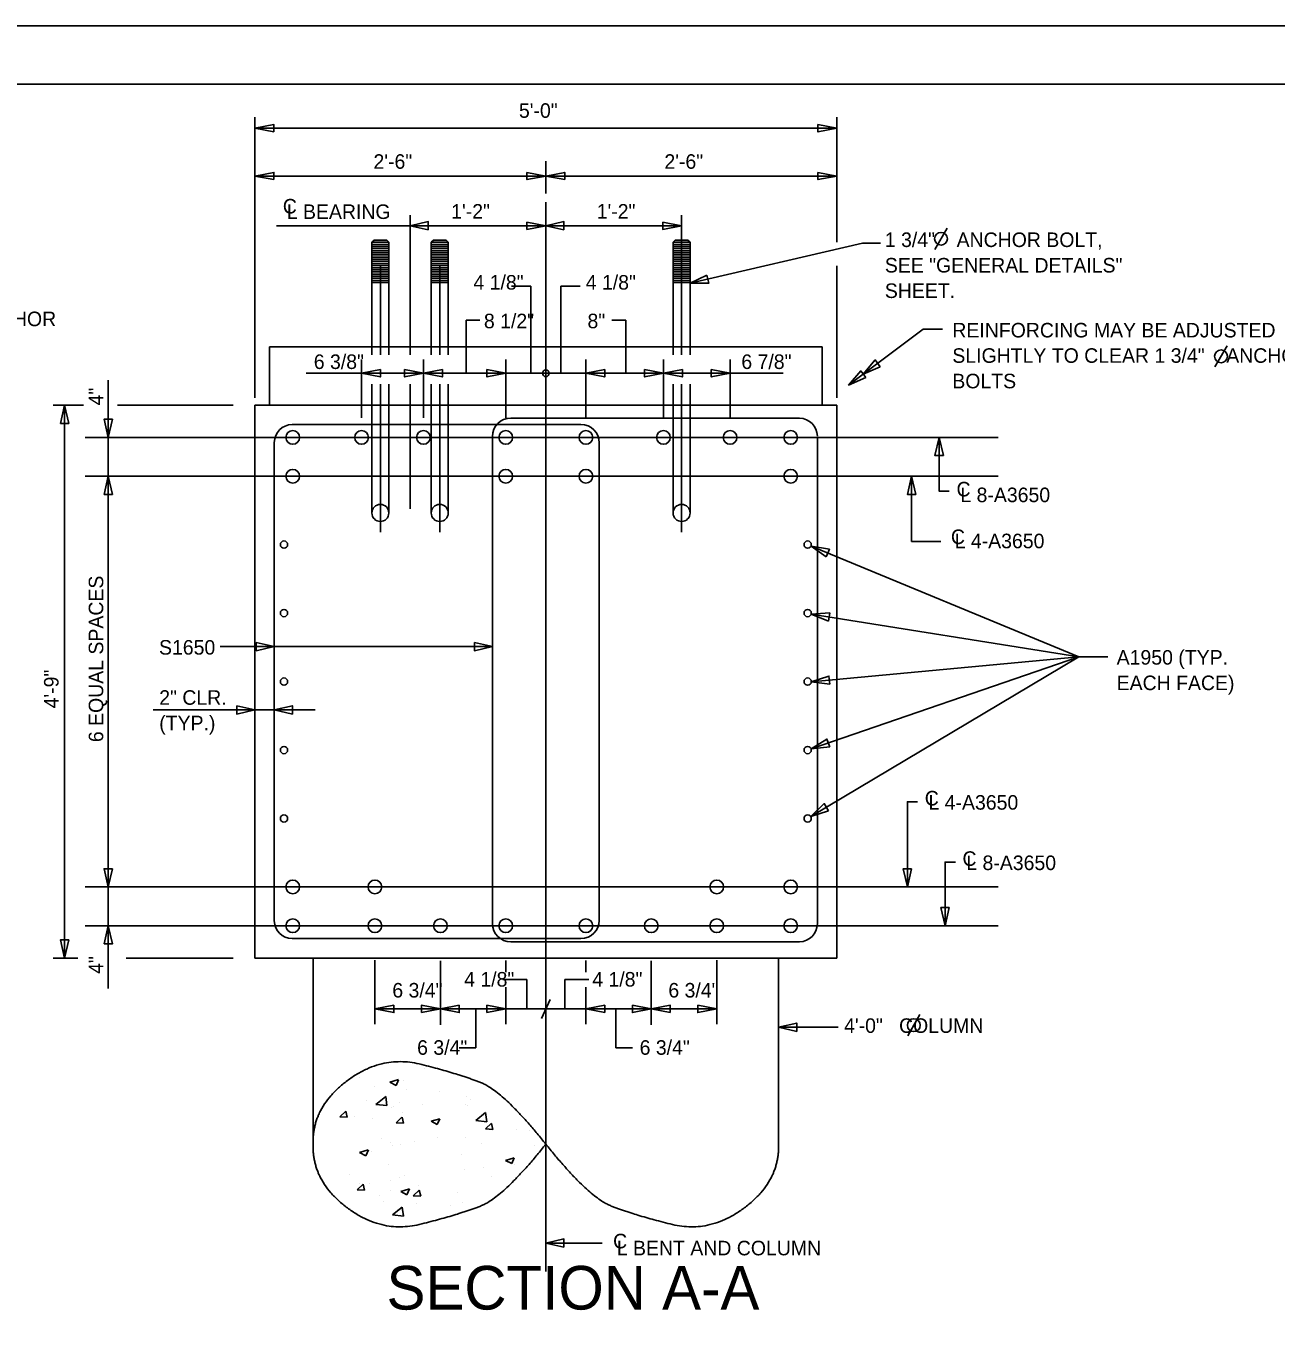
# Model space of a CAD drawing. Extents: x -133.1 to -97, y -1.7 to 20.3.
# Drawn here: x -120.43 to -109.68, y 9.2 to 20.31 of the extents above; entities that cross this region are included whole.
import ezdxf

# ---------------------------------------------------------------- set-up
doc = ezdxf.new("R2010")
doc.units = 0
for name, color, linetype in [('BR_AUTO DIMENSION', 7, 'Continuous'), ('BR_BORDER LINES', 7, 'Continuous'), ('BR_CENTER LINES', 7, 'Continuous'), ('BR_CONCRETE', 7, 'Continuous'), ('BR_REBAR', 7, 'Continuous'), ('BR_STRUCTURAL STEEL', 7, 'Continuous'), ('BR_TEXT', 7, 'Continuous'), ('Level 31', 7, 'Continuous')]:
    doc.layers.add(name, color=color, linetype=linetype)

msp = doc.modelspace()

# ---------------------------------------------------------------- linework, layer by layer
at = {"layer": 'BR_AUTO DIMENSION'}
for p, q in [((-118.457, 17.113), (-118.457, 19.526)), ((-113.457, 18.452), (-113.457, 19.526)), ((-118.457, 19.429), (-113.457, 19.429)), ((-115.957, 18.87), (-115.957, 19.147)), ((-118.457, 19.019), (-115.957, 19.019)), ((-113.457, 19.019), (-115.957, 19.019)), ((-118.271, 18.592), (-114.79, 18.592)), ((-114.717, 18.098), (-113.235, 18.442)), ((-113.235, 18.442), (-113.082, 18.442)), ((-113.457, 17.113), (-113.457, 18.247)), ((-116.087, 18.072), (-116.251, 18.072)), ((-116.087, 17.324), (-116.087, 18.072)), ((-115.827, 17.324), (-115.827, 18.072)), ((-115.827, 18.072), (-115.663, 18.072)), ((-116.642, 17.324), (-116.642, 17.78)), ((-116.642, 17.78), (-116.524, 17.78)), ((-115.271, 17.78), (-115.389, 17.78)), ((-115.271, 17.324), (-115.271, 17.78)), ((-117.54, 16.94), (-117.54, 17.443)), ((-117.009, 16.94), (-117.009, 17.443)), ((-116.301, 16.94), (-116.301, 17.443)), ((-115.613, 16.94), (-115.613, 17.443)), ((-114.946, 16.94), (-114.946, 17.443)), ((-114.373, 16.94), (-114.373, 17.443)), ((-119.717, 17.265), (-119.717, 12.039)), ((-118.017, 17.324), (-113.918, 17.324)), ((-119.93, 17.05), (-120.19, 17.05)), ((-120.092, 17.05), (-120.092, 12.3)), ((-118.644, 17.05), (-119.639, 17.05)), ((-112.814, 16.44), (-112.814, 15.878)), ((-111.376, 14.889), (-113.678, 15.839)), ((-112.814, 15.878), (-112.563, 15.878)), ((-111.376, 14.889), (-113.677, 15.254)), ((-116.415, 14.976), (-118.756, 14.976)), ((-111.376, 14.889), (-113.68, 13.516)), ((-111.376, 14.889), (-113.676, 14.673)), ((-117.939, 14.432), (-119.331, 14.432)), ((-119.979, 12.3), (-120.19, 12.3)), ((-118.644, 12.3), (-119.562, 12.3)), ((-117.426, 11.731), (-117.426, 12.282)), ((-116.863, 11.725), (-116.863, 12.277)), ((-116.301, 12.179), (-116.301, 12.278)), ((-115.613, 12.179), (-115.613, 12.278)), ((-115.051, 11.725), (-115.051, 12.277)), ((-114.488, 11.731), (-114.488, 12.282)), ((-116.119, 12.117), (-116.326, 12.117)), ((-116.119, 11.863), (-116.119, 12.117)), ((-115.794, 11.863), (-115.794, 12.117)), ((-115.794, 12.117), (-115.588, 12.117)), ((-116.301, 11.731), (-116.301, 12.049)), ((-115.613, 11.731), (-115.613, 12.049)), ((-115.994, 11.78), (-115.92, 11.945)), ((-114.488, 11.863), (-117.426, 11.863)), ((-116.558, 11.863), (-116.558, 11.53)), ((-115.356, 11.863), (-115.356, 11.53)), ((-113.957, 11.705), (-113.445, 11.705)), ((-116.558, 11.53), (-116.702, 11.53)), ((-115.355, 11.53), (-115.212, 11.53)), ((-115.957, 9.851), (-115.474, 9.851))]:
    msp.add_line(p, q, dxfattribs=at)
for points in [[(-118.294, 19.398), (-118.457, 19.429), (-118.294, 19.461)], [(-113.619, 19.461), (-113.457, 19.429), (-113.619, 19.398)], [(-118.294, 18.988), (-118.457, 19.019), (-118.294, 19.05)], [(-116.119, 19.05), (-115.957, 19.019), (-116.119, 18.988)], [(-115.794, 18.988), (-115.957, 19.019), (-115.794, 19.05)], [(-113.619, 19.05), (-113.457, 19.019), (-113.619, 18.988)], [(-116.968, 18.556), (-117.124, 18.592), (-116.968, 18.628)], [(-116.119, 18.623), (-115.957, 18.592), (-116.119, 18.56)], [(-115.801, 18.556), (-115.957, 18.592), (-115.801, 18.628)], [(-114.953, 18.623), (-114.79, 18.592), (-114.953, 18.56)], [(-114.573, 18.168), (-114.717, 18.098), (-114.557, 18.098)], [(-117.378, 17.356), (-117.54, 17.324), (-117.378, 17.293)], [(-117.171, 17.356), (-117.009, 17.324), (-117.171, 17.293)], [(-116.846, 17.356), (-117.009, 17.324), (-116.846, 17.293)], [(-116.463, 17.356), (-116.301, 17.324), (-116.463, 17.293)], [(-115.451, 17.356), (-115.613, 17.324), (-115.451, 17.293)], [(-115.109, 17.356), (-114.946, 17.324), (-115.109, 17.293)], [(-114.784, 17.356), (-114.946, 17.324), (-114.784, 17.293)], [(-114.536, 17.356), (-114.374, 17.324), (-114.536, 17.293)], [(-113.208, 17.288), (-113.355, 17.223), (-113.251, 17.345)], [(-113.083, 17.381), (-113.23, 17.316), (-113.126, 17.439)], [(-120.128, 16.894), (-120.092, 17.05), (-120.056, 16.894)], [(-119.681, 16.929), (-119.717, 16.773), (-119.753, 16.929)], [(-112.541, 16.617), (-112.577, 16.773), (-112.613, 16.617)], [(-119.753, 16.284), (-119.717, 16.44), (-119.681, 16.284)], [(-112.778, 16.284), (-112.814, 16.44), (-112.85, 16.284)], [(-113.548, 15.746), (-113.678, 15.839), (-113.52, 15.813)], [(-113.529, 15.194), (-113.677, 15.254), (-113.517, 15.265)], [(-118.446, 15.012), (-118.29, 14.976), (-118.446, 14.94)], [(-116.571, 15.012), (-116.415, 14.976), (-116.571, 14.94)], [(-113.517, 14.652), (-113.676, 14.673), (-113.524, 14.723)], [(-118.613, 14.468), (-118.457, 14.432), (-118.613, 14.396)], [(-118.134, 14.396), (-118.29, 14.432), (-118.134, 14.468)], [(-113.518, 14.114), (-113.677, 14.098), (-113.542, 14.182)], [(-113.528, 13.565), (-113.68, 13.516), (-113.565, 13.627)], [(-119.681, 13.067), (-119.717, 12.911), (-119.753, 13.067)], [(-112.814, 13.067), (-112.85, 12.911), (-112.886, 13.067)], [(-112.49, 12.734), (-112.526, 12.578), (-112.562, 12.734)], [(-119.753, 12.422), (-119.717, 12.578), (-119.681, 12.422)], [(-120.056, 12.456), (-120.092, 12.3), (-120.128, 12.456)], [(-117.263, 11.894), (-117.426, 11.863), (-117.263, 11.831)], [(-117.026, 11.831), (-116.863, 11.863), (-117.026, 11.894)], [(-116.701, 11.894), (-116.863, 11.863), (-116.701, 11.831)], [(-116.463, 11.831), (-116.301, 11.863), (-116.463, 11.894)], [(-115.451, 11.831), (-115.613, 11.863), (-115.451, 11.894)], [(-115.213, 11.894), (-115.051, 11.863), (-115.213, 11.831)], [(-114.888, 11.831), (-115.051, 11.863), (-114.888, 11.894)], [(-114.651, 11.894), (-114.488, 11.863), (-114.651, 11.831)], [(-113.801, 11.669), (-113.957, 11.705), (-113.801, 11.741)], [(-115.801, 9.815), (-115.957, 9.851), (-115.801, 9.887)]]:
    msp.add_lwpolyline(points, close=True, dxfattribs=at)
for points in [[(-113.355, 17.223), (-112.714, 17.702), (-112.549, 17.702)], [(-112.577, 16.773), (-112.577, 16.31), (-112.49, 16.31)], [(-113.677, 14.098), (-111.376, 14.889), (-111.129, 14.889)], [(-112.85, 12.911), (-112.85, 13.643), (-112.763, 13.643)], [(-112.526, 12.578), (-112.526, 13.124), (-112.438, 13.124)]]:
    msp.add_lwpolyline(points, dxfattribs=at)
msp.add_circle((-115.957, 17.324), 0.0285, dxfattribs=at)
at = {"layer": 'BR_BORDER LINES'}
msp.add_line((-97.642, 19.809), (-131.308, 19.809), dxfattribs=at)
at = {"layer": 'BR_CENTER LINES'}
for p, q in [((-115.957, 18.793), (-115.957, 9.608)), ((-117.124, 18.683), (-117.124, 17.482)), ((-114.79, 18.683), (-114.79, 17.482)), ((-117.379, 17.482), (-117.379, 18.257)), ((-116.869, 17.482), (-116.869, 18.257)), ((-114.79, 17.482), (-114.79, 18.257)), ((-117.379, 15.958), (-117.379, 17.23)), ((-117.124, 17.23), (-117.124, 16.161)), ((-116.869, 15.958), (-116.869, 17.23)), ((-114.79, 15.958), (-114.79, 17.23)), ((-119.915, 16.773), (-112.07, 16.773)), ((-119.915, 16.44), (-112.07, 16.44)), ((-119.915, 12.911), (-112.07, 12.911)), ((-119.915, 12.578), (-112.07, 12.578))]:
    msp.add_line(p, q, dxfattribs=at)
at = {"layer": 'BR_CONCRETE'}
for p, q in [((-118.332, 17.551), (-118.332, 17.05)), ((-118.332, 17.551), (-113.582, 17.551)), ((-113.582, 17.551), (-113.582, 17.05)), ((-118.457, 17.05), (-118.457, 12.3)), ((-118.457, 17.05), (-113.457, 17.05)), ((-113.457, 17.05), (-113.457, 12.3)), ((-118.457, 12.3), (-113.457, 12.3)), ((-117.957, 12.3), (-117.957, 10.669)), ((-113.957, 12.3), (-113.957, 10.668)), ((-117, 11.347), (-117, 11.347)), ((-117.558, 11.278), (-117.558, 11.278)), ((-117.297, 11.233), (-117.222, 11.256)), ((-117.297, 11.233), (-117.244, 11.205)), ((-117.243, 11.205), (-117.222, 11.255)), ((-117.177, 11.25), (-117.177, 11.25)), ((-117.432, 11.197), (-117.432, 11.197)), ((-117.156, 11.171), (-117.156, 11.171)), ((-116.87, 11.152), (-116.87, 11.152)), ((-117.502, 11.077), (-117.502, 11.077)), ((-117.417, 11.043), (-117.333, 11.111)), ((-117.417, 11.043), (-117.322, 11.032)), ((-117.322, 11.032), (-117.333, 11.111)), ((-117.282, 11.018), (-117.282, 11.018)), ((-117.262, 11.023), (-117.262, 11.023)), ((-117.216, 11.059), (-117.216, 11.059)), ((-117.014, 11.046), (-117.014, 11.046)), ((-116.644, 11.04), (-116.644, 11.04)), ((-116.637, 11.107), (-116.637, 11.107)), ((-116.633, 11.035), (-116.633, 11.035)), ((-116.608, 11.088), (-116.608, 11.088)), ((-117.727, 10.937), (-117.675, 10.985)), ((-117.727, 10.937), (-117.663, 10.933)), ((-117.663, 10.933), (-117.675, 10.985)), ((-117.673, 10.949), (-117.673, 10.949)), ((-117.601, 10.94), (-117.601, 10.94)), ((-117.445, 10.919), (-117.445, 10.919)), ((-117.244, 10.885), (-117.193, 10.933)), ((-117.18, 10.881), (-117.192, 10.933)), ((-117.19, 10.973), (-117.19, 10.973)), ((-116.943, 10.898), (-116.868, 10.92)), ((-116.943, 10.898), (-116.89, 10.87)), ((-116.89, 10.87), (-116.868, 10.92)), ((-116.559, 10.905), (-116.476, 10.973)), ((-116.559, 10.905), (-116.464, 10.894)), ((-116.464, 10.894), (-116.476, 10.973)), ((-117.244, 10.885), (-117.18, 10.881)), ((-116.476, 10.833), (-116.424, 10.881)), ((-116.476, 10.833), (-116.412, 10.828)), ((-116.412, 10.828), (-116.424, 10.88)), ((-116.213, 10.828), (-116.213, 10.828)), ((-116.096, 10.817), (-116.096, 10.817)), ((-117.369, 10.747), (-117.369, 10.747)), ((-117.296, 10.717), (-117.296, 10.717)), ((-117.278, 10.69), (-117.278, 10.69)), ((-117.203, 10.695), (-117.203, 10.695)), ((-117.083, 10.728), (-117.083, 10.728)), ((-116.89, 10.759), (-116.89, 10.759)), ((-116.646, 10.758), (-116.646, 10.758)), ((-116.511, 10.709), (-116.511, 10.709)), ((-116.056, 10.693), (-116.056, 10.693)), ((-117.558, 10.629), (-117.483, 10.651)), ((-117.558, 10.629), (-117.504, 10.601)), ((-117.504, 10.601), (-117.482, 10.651)), ((-117.458, 10.642), (-117.458, 10.642)), ((-116.681, 10.609), (-116.681, 10.609)), ((-116.303, 10.562), (-116.228, 10.585)), ((-116.303, 10.562), (-116.25, 10.534)), ((-116.25, 10.534), (-116.228, 10.584)), ((-117.306, 10.526), (-117.306, 10.526)), ((-116.659, 10.48), (-116.659, 10.48)), ((-116.495, 10.499), (-116.495, 10.499)), ((-116.227, 10.527), (-116.227, 10.527)), ((-116.109, 10.539), (-116.109, 10.539)), ((-117.645, 10.443), (-117.645, 10.443)), ((-117.578, 10.31), (-117.527, 10.358)), ((-117.56, 10.361), (-117.56, 10.361)), ((-117.514, 10.306), (-117.527, 10.358)), ((-117.471, 10.365), (-117.471, 10.365)), ((-117.292, 10.389), (-117.292, 10.389)), ((-117.216, 10.418), (-117.216, 10.418)), ((-117.172, 10.43), (-117.172, 10.43)), ((-117.049, 10.343), (-117.049, 10.343)), ((-116.424, 10.426), (-116.424, 10.426)), ((-117.578, 10.321), (-117.578, 10.321)), ((-117.578, 10.31), (-117.514, 10.306)), ((-117.388, 10.26), (-117.388, 10.26)), ((-117.292, 10.302), (-117.292, 10.302)), ((-117.204, 10.293), (-117.129, 10.316)), ((-117.204, 10.293), (-117.15, 10.265)), ((-117.15, 10.265), (-117.129, 10.316)), ((-117.096, 10.258), (-117.044, 10.306)), ((-117.096, 10.258), (-117.031, 10.254)), ((-117.031, 10.254), (-117.044, 10.306)), ((-116.72, 10.284), (-116.72, 10.284)), ((-117.352, 10.209), (-117.352, 10.209)), ((-117.275, 10.094), (-117.191, 10.161)), ((-117.229, 10.141), (-117.229, 10.141)), ((-117.179, 10.082), (-117.191, 10.161)), ((-117.066, 10.19), (-117.066, 10.19)), ((-116.777, 10.171), (-116.777, 10.171)), ((-116.672, 10.203), (-116.672, 10.203)), ((-117.275, 10.094), (-117.18, 10.082)), ((-117.168, 10.101), (-117.168, 10.101))]:
    msp.add_line(p, q, dxfattribs=at)
for points in [[(-117.957, 10.701), (-117.967, 11.017), (-117.368, 11.47), (-116.707, 11.307), (-116.318, 11.151), (-115.957, 10.701)], [(-117.957, 10.701), (-117.967, 10.384), (-117.368, 9.931), (-116.707, 10.094), (-116.318, 10.25), (-115.957, 10.701)], [(-113.957, 10.701), (-113.947, 10.384), (-114.546, 9.931), (-115.206, 10.094), (-115.595, 10.25), (-115.957, 10.701)]]:
    msp.add_open_spline(points, degree=2, dxfattribs=at)
at = {"layer": 'BR_REBAR'}
for p, q in [((-113.777, 16.938), (-116.259, 16.938)), ((-118.136, 16.884), (-115.655, 16.884)), ((-116.415, 16.782), (-116.415, 12.596)), ((-113.624, 16.779), (-113.624, 12.594)), ((-118.29, 16.73), (-118.29, 12.621)), ((-115.499, 16.728), (-115.499, 12.623)), ((-118.136, 12.467), (-115.655, 12.467)), ((-113.777, 12.44), (-116.259, 12.44))]:
    msp.add_line(p, q, dxfattribs=at)
for centre, radius in [((-118.132, 16.773), 0.0588), ((-117.54, 16.773), 0.0588), ((-117.009, 16.773), 0.0588), ((-116.301, 16.773), 0.0588), ((-115.613, 16.773), 0.0588), ((-114.946, 16.773), 0.0588), ((-114.374, 16.773), 0.0588), ((-113.853, 16.773), 0.0588), ((-118.132, 16.44), 0.0588), ((-116.301, 16.44), 0.0588), ((-115.613, 16.44), 0.0588), ((-113.853, 16.44), 0.0588), ((-118.207, 15.852), 0.0313), ((-113.707, 15.852), 0.0313), ((-118.207, 15.264), 0.0313), ((-113.707, 15.264), 0.0313), ((-118.207, 14.675), 0.0313), ((-113.707, 14.675), 0.0313), ((-118.207, 14.087), 0.0313), ((-113.707, 14.087), 0.0313), ((-118.207, 13.499), 0.0313), ((-113.707, 13.499), 0.0313), ((-118.132, 12.911), 0.0588), ((-117.426, 12.911), 0.0588), ((-114.488, 12.911), 0.0588), ((-113.853, 12.911), 0.0588), ((-118.132, 12.578), 0.0588), ((-117.426, 12.578), 0.0588), ((-116.863, 12.578), 0.0588), ((-116.301, 12.578), 0.0588), ((-115.613, 12.578), 0.0588), ((-115.051, 12.578), 0.0588), ((-114.488, 12.578), 0.0588), ((-113.853, 12.578), 0.0588)]:
    msp.add_circle(centre, radius, dxfattribs=at)
for centre, start, end in [((-116.259, 16.782), 90, 180), ((-113.78, 16.782), 1.025, 88.975), ((-118.134, 16.728), 91.025, 178.975), ((-115.655, 16.728), 0, 90), ((-118.134, 12.623), 181.025, 268.975), ((-116.259, 12.596), 180, 270), ((-115.655, 12.623), 270, 0), ((-113.78, 12.596), 271.025, 358.975)]:
    msp.add_arc(centre, 0.156, start, end, dxfattribs=at)
at = {"layer": 'BR_STRUCTURAL STEEL'}
for p, q in [((-117.452, 18.45), (-117.433, 18.468)), ((-117.452, 18.45), (-117.306, 18.45)), ((-117.452, 18.45), (-117.452, 17.482)), ((-117.433, 18.468), (-117.324, 18.468)), ((-117.324, 18.468), (-117.306, 18.45)), ((-117.306, 18.45), (-117.306, 17.482)), ((-116.942, 18.45), (-116.923, 18.468)), ((-116.942, 18.45), (-116.796, 18.45)), ((-116.942, 18.45), (-116.942, 17.482)), ((-116.923, 18.468), (-116.814, 18.468)), ((-116.814, 18.468), (-116.796, 18.45)), ((-116.796, 18.45), (-116.796, 17.482)), ((-114.863, 18.45), (-114.845, 18.468)), ((-114.863, 18.45), (-114.717, 18.45)), ((-114.863, 18.45), (-114.863, 17.482)), ((-114.845, 18.468), (-114.736, 18.468)), ((-114.736, 18.468), (-114.717, 18.45)), ((-114.717, 18.45), (-114.717, 17.482)), ((-117.452, 18.432), (-117.306, 18.432)), ((-117.452, 18.414), (-117.306, 18.414)), ((-117.452, 18.395), (-117.306, 18.395)), ((-117.452, 18.377), (-117.306, 18.377)), ((-117.452, 18.359), (-117.306, 18.359)), ((-117.452, 18.341), (-117.306, 18.341)), ((-116.942, 18.432), (-116.796, 18.432)), ((-116.942, 18.414), (-116.796, 18.414)), ((-116.942, 18.395), (-116.796, 18.395)), ((-116.942, 18.377), (-116.796, 18.377)), ((-116.942, 18.359), (-116.796, 18.359)), ((-116.942, 18.341), (-116.796, 18.341)), ((-114.863, 18.432), (-114.717, 18.432)), ((-114.863, 18.414), (-114.717, 18.414)), ((-114.863, 18.395), (-114.717, 18.395)), ((-114.863, 18.377), (-114.717, 18.377)), ((-114.863, 18.359), (-114.717, 18.359)), ((-114.863, 18.341), (-114.717, 18.341)), ((-117.452, 18.323), (-117.306, 18.323)), ((-117.452, 18.304), (-117.306, 18.304)), ((-117.452, 18.286), (-117.306, 18.286)), ((-117.452, 18.268), (-117.306, 18.268)), ((-117.452, 18.25), (-117.306, 18.25)), ((-117.452, 18.231), (-117.306, 18.231)), ((-116.942, 18.323), (-116.796, 18.323)), ((-116.942, 18.304), (-116.796, 18.304)), ((-116.942, 18.286), (-116.796, 18.286)), ((-116.942, 18.268), (-116.796, 18.268)), ((-116.942, 18.25), (-116.796, 18.25)), ((-116.942, 18.231), (-116.796, 18.231)), ((-114.863, 18.323), (-114.717, 18.323)), ((-114.863, 18.304), (-114.717, 18.304)), ((-114.863, 18.286), (-114.717, 18.286)), ((-114.863, 18.268), (-114.717, 18.268)), ((-114.863, 18.25), (-114.717, 18.25)), ((-114.863, 18.231), (-114.717, 18.231)), ((-117.452, 18.213), (-117.306, 18.213)), ((-117.452, 18.195), (-117.306, 18.195)), ((-117.452, 18.177), (-117.306, 18.177)), ((-117.452, 18.158), (-117.306, 18.158)), ((-117.452, 18.14), (-117.306, 18.14)), ((-117.452, 18.122), (-117.306, 18.122)), ((-116.942, 18.213), (-116.796, 18.213)), ((-116.942, 18.195), (-116.796, 18.195)), ((-116.942, 18.177), (-116.796, 18.177)), ((-116.942, 18.158), (-116.796, 18.158)), ((-116.942, 18.14), (-116.796, 18.14)), ((-116.942, 18.122), (-116.796, 18.122)), ((-114.863, 18.213), (-114.717, 18.213)), ((-114.863, 18.195), (-114.717, 18.195)), ((-114.863, 18.177), (-114.717, 18.177)), ((-114.863, 18.158), (-114.717, 18.158)), ((-114.863, 18.14), (-114.717, 18.14)), ((-114.863, 18.122), (-114.717, 18.122)), ((-117.452, 18.104), (-117.306, 18.104)), ((-116.942, 18.104), (-116.796, 18.104)), ((-114.863, 18.104), (-114.717, 18.104)), ((-117.452, 17.23), (-117.451, 16.127)), ((-117.306, 17.23), (-117.306, 16.124)), ((-116.941, 17.23), (-116.941, 16.127)), ((-116.796, 17.23), (-116.796, 16.124)), ((-114.863, 17.23), (-114.863, 16.127)), ((-114.717, 17.23), (-114.717, 16.124))]:
    msp.add_line(p, q, dxfattribs=at)
for centre in [(-117.379, 16.124), (-116.869, 16.124), (-114.79, 16.124)]:
    msp.add_circle(centre, 0.0729, dxfattribs=at)
at = {"layer": 'BR_TEXT'}
for p, q in [((-112.613, 18.389), (-112.508, 18.57)), ((-110.207, 17.379), (-110.102, 17.561)), ((-120.092, 12.3), (-120.092, 12.448)), ((-112.847, 11.632), (-112.742, 11.814))]:
    msp.add_line(p, q, dxfattribs=at)
for centre in [(-112.561, 18.48), (-110.155, 17.47), (-112.795, 11.723)]:
    msp.add_circle(centre, 0.055, dxfattribs=at)
at = {"layer": 'Level 31'}
msp.add_lwpolyline([(-133.141, -1.691), (-97.141, -1.691), (-97.141, 20.309), (-133.141, 20.309)], close=True, dxfattribs=at)

# ---------------------------------------------------------------- texts
at = {"layer": 'BR_AUTO DIMENSION'}
for s, p in [('5\'-0"', (-116.188, 19.519)), ('2\'-6"', (-117.438, 19.081)), ('2\'-6"', (-114.938, 19.081)), ('4 1/8"', (-116.579, 18.043)), ('4 1/8"', (-115.614, 18.043)), ('8 1/2"', (-116.489, 17.711)), ('8"', (-115.599, 17.711)), ('6 3/8"', (-117.951, 17.361)), ('6 7/8"', (-114.277, 17.361))]:
    msp.add_text(s, height=0.125, dxfattribs=at).set_placement(p)
at = {"layer": 'BR_TEXT'}
for s, rotation, p in [('C', 360, (-118.217, 18.697)), ('1\'-2"', 360, (-116.77, 18.653)), ('1\'-2"', 360, (-115.52, 18.653)), ('L BEARING', 360, (-118.183, 18.65)), ('1 3/4"    ANCHOR BOLT, ', 360, (-113.044, 18.409)), ('SEE "GENERAL DETAILS"', 360, (-113.044, 18.19)), ('SHEET.', 360, (-113.044, 17.971)), ('SLIGHTLY TO CLEAR 1 3/4"    ANCHOR', 360, (-123.243, 17.729)), ('REINFORCING MAY BE ADJUSTED', 360, (-112.464, 17.632)), ('SLIGHTLY TO CLEAR 1 3/4"    ANCHOR', 360, (-112.464, 17.414)), ('BOLTS', 360, (-112.464, 17.195)), ('4"', 90, (-119.76, 17.048)), ('C', 360, (-112.428, 16.266)), ('L 8-A3650', 360, (-112.395, 16.217)), ('C', 360, (-112.476, 15.857)), ('L 4-A3650', 360, (-112.444, 15.821)), ('6 EQUAL SPACES', 90, (-119.76, 14.155)), ('S1650', 360, (-119.281, 14.907)), ('A1950 (TYP.', 360, (-111.052, 14.821)), ('4\'-9"', 90, (-120.144, 14.445)), ('EACH FACE)', 360, (-111.052, 14.602)), ('2" CLR.', 360, (-119.279, 14.476)), ('(TYP.)', 360, (-119.279, 14.257)), ('C', 360, (-112.701, 13.611)), ('L 4-A3650', 360, (-112.669, 13.575)), ('C', 360, (-112.377, 13.092)), ('L 8-A3650', 360, (-112.344, 13.056)), ('4"', 90, (-119.76, 12.164)), ('6 3/4"', 360, (-117.276, 11.961)), ('6 3/4"', 360, (-114.904, 11.961)), ('4\'-0"   COLUMN', 360, (-113.394, 11.657)), ('6 3/4"', 360, (-117.063, 11.469)), ('6 3/4"', 360, (-115.151, 11.469)), ('C', 360, (-115.379, 9.806)), ('L BENT AND COLUMN', 360, (-115.347, 9.746))]:
    msp.add_text(s, height=0.125, rotation=rotation, dxfattribs=at).set_placement(p)
for s, height, p in [('4 1/8"', 0.125, (-116.659, 12.055)), ('4 1/8"', 0.125, (-115.558, 12.055)), ('SECTION A-A', 0.375, (-117.326, 9.28))]:
    msp.add_text(s, height=height, dxfattribs=at).set_placement(p)

doc.saveas('drawing.dxf')
